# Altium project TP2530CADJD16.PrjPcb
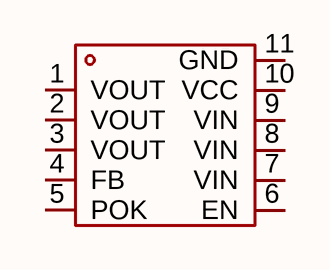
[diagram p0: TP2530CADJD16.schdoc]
1 sheet, 1 parts. Net scope: global (net labels, ports and power ports of the same name join across sheets).

## Sheet TP2530CADJD16.schdoc
size 127 x 101 mm

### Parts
U?  tp2530cadjd16  [DFN-10_L3.0-W3.0-P0.50-BL-EP2.5-1]  (value not drawn)

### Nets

Not connected (* = marked no-connect by the designer): U? 1(VOUT) 2(VOUT) 3(VOUT) 4(FB) 5(POK) 6(EN) 7(VIN) 8(VIN) 9(VIN) 10(VCC) 11(GND)

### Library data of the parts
U? = tp2530cadjd16: 输出极性:正极;工作电压:6V;输出电压:-;输出电流:3A;电源纹波抑制比(PSRR):-;输出类型:可调;; Manufacturer: TECH PUBLIC(台舟); AddInBom: yes; ModelId: 7fe0d695ab96406c9a668c503a8ee090; ModelTransform: 118.11,118.11,0,0,0,0,0,0.005,0; Output Configuration: 正极; Voltage - Supply: 6V; Output Current: 3A; Voltage Dropout: 250mV@(3A); standby current: 900uA; Output Type: 可调; Number of Outputs: 1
